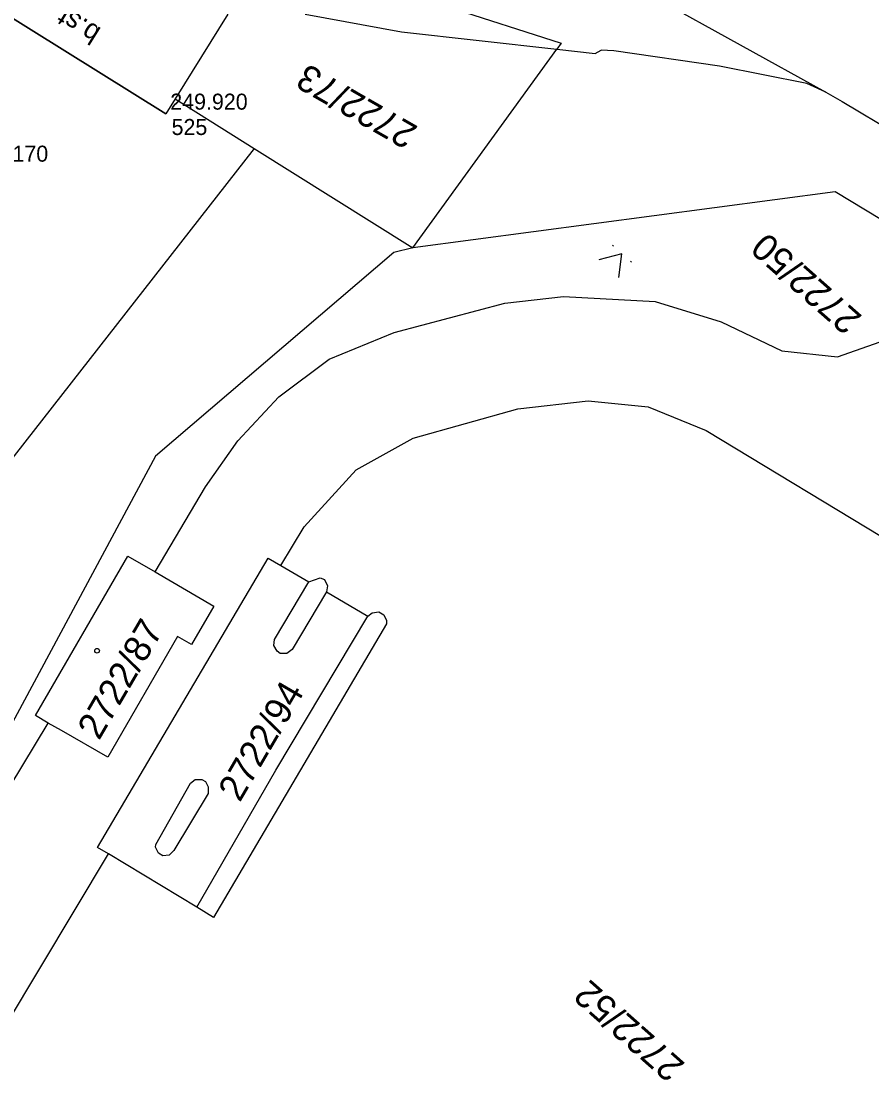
# Model space of a CAD drawing. Extents: x -496688 to -495455, y -1089309 to -1088026.
# Drawn here: x -495849.8 to -495786, y -1088485.3 to -1088405.9 of the extents above; entities that cross this region are included whole.
import ezdxf

# ---------------------------------------------------------------- set-up
doc = ezdxf.new("R2010")
doc.units = 0
for name, color, linetype in [('Vrstva 23', 7, 'Continuous'), ('Vrstva 53', 7, 'Continuous'), ('Vrstva 55', 7, 'Continuous'), ('Vrstva 56', 7, 'Continuous'), ('Vrstva 57', 7, 'Continuous'), ('Vrstva 58', 7, 'Continuous'), ('Vrstva 59', 7, 'Continuous'), ('Vrstva 60', 7, 'Continuous'), ('Vrstva 61', 7, 'Continuous')]:
    doc.layers.add(name, color=color, linetype=linetype)

msp = doc.modelspace()

# ---------------------------------------------------------------- linework, layer by layer
at = {"layer": 'Vrstva 23'}
for p, q in [((-495838.95, -1088412.85), (-495854.72, -1088403.04)), ((-495834.31, -1088405.39), (-495838.26, -1088411.74)), ((-495838.26, -1088411.74), (-495838.95, -1088412.85)), ((-495848.73, -1088457.96), (-495841.81, -1088446.01)), ((-495841.81, -1088446.01), (-495839.76, -1088447.2)), ((-495839.76, -1088447.2), (-495835.35, -1088449.77)), ((-495835.35, -1088449.77), (-495837.03, -1088452.64)), ((-495838.07, -1088452.04), (-495843.3, -1088461.09)), ((-495837.03, -1088452.64), (-495838.07, -1088452.04)), ((-495847.77, -1088458.53), (-495848.73, -1088457.96)), ((-495846.78, -1088459.09), (-495847.77, -1088458.53)), ((-495843.3, -1088461.09), (-495846.78, -1088459.09))]:
    msp.add_line(p, q, dxfattribs=at)
at = {"layer": 'Vrstva 53'}
for p, q in [((-495854.72, -1088403.04), (-495838.95, -1088412.85)), ((-495838.26, -1088411.74), (-495838.95, -1088412.85)), ((-495838.26, -1088411.74), (-495832.32, -1088415.46)), ((-495832.32, -1088415.46), (-495856.5, -1088446.39))]:
    msp.add_line(p, q, dxfattribs=at)
at = {"layer": 'Vrstva 55'}
for p, q in [((-495818.51, -1088395.14), (-495789.48, -1088411.23)), ((-495828.5, -1088405.37), (-495821.29, -1088406.71)), ((-495817.9, -1088404.8), (-495809.31, -1088407.56)), ((-495821.29, -1088406.71), (-495809.63, -1088408)), ((-495809.31, -1088407.56), (-495809.63, -1088408)), ((-495820.43, -1088422.89), (-495809.63, -1088408)), ((-495809.63, -1088408), (-495806.76, -1088408.32)), ((-495806.76, -1088408.32), (-495806.33, -1088408.09)), ((-495805.36, -1088408.14), (-495806.33, -1088408.09)), ((-495797.45, -1088409.29), (-495805.36, -1088408.14)), ((-495790.91, -1088410.59), (-495797.45, -1088409.29)), ((-495789.48, -1088411.23), (-495790.91, -1088410.59)), ((-495789.48, -1088411.23), (-495788.25, -1088411.92)), ((-495788.25, -1088411.92), (-495734.16, -1088444.4)), ((-495832.32, -1088415.46), (-495820.43, -1088422.89)), ((-495788.77, -1088418.71), (-495820.43, -1088422.89)), ((-495779.45, -1088424.37), (-495788.77, -1088418.71)), ((-495821.85, -1088423.26), (-495839.72, -1088438.53)), ((-495820.43, -1088422.89), (-495821.85, -1088423.26)), ((-495813.54, -1088427.04), (-495809.14, -1088426.54)), ((-495809.14, -1088426.54), (-495802.28, -1088426.92)), ((-495821.83, -1088429.25), (-495813.54, -1088427.04)), ((-495802.28, -1088426.92), (-495797.33, -1088428.45)), ((-495797.33, -1088428.45), (-495792.78, -1088430.61)), ((-495826.72, -1088431.25), (-495821.83, -1088429.25)), ((-495788.6, -1088431.07), (-495784.99, -1088429.8)), ((-495792.78, -1088430.61), (-495788.6, -1088431.07)), ((-495830.48, -1088434.07), (-495826.72, -1088431.25)), ((-495833.56, -1088437.37), (-495830.48, -1088434.07)), ((-495812.56, -1088434.98), (-495807.29, -1088434.37)), ((-495807.29, -1088434.37), (-495802.8, -1088434.81)), ((-495820.42, -1088437.16), (-495812.56, -1088434.98)), ((-495802.8, -1088434.81), (-495798.45, -1088436.59)), ((-495798.45, -1088436.59), (-495751.96, -1088464.75)), ((-495835.98, -1088440.81), (-495833.56, -1088437.37)), ((-495824.68, -1088439.55), (-495820.42, -1088437.16)), ((-495839.72, -1088438.53), (-495862.56, -1088480.87)), ((-495828.58, -1088443.81), (-495824.68, -1088439.55)), ((-495839.76, -1088447.2), (-495835.98, -1088440.81)), ((-495830.32, -1088446.72), (-495828.58, -1088443.81)), ((-495844.08, -1088467.85), (-495831.28, -1088446.17)), ((-495831.28, -1088446.17), (-495830.32, -1088446.72)), ((-495830.32, -1088446.72), (-495828.24, -1088447.93)), ((-495828.24, -1088447.93), (-495827.39, -1088447.64)), ((-495827.39, -1088447.64), (-495827.07, -1088447.76)), ((-495827.07, -1088447.76), (-495826.83, -1088448.23)), ((-495826.83, -1088448.23), (-495826.91, -1088448.7)), ((-495826.91, -1088448.7), (-495829.48, -1088453.01)), ((-495826.91, -1088448.7), (-495823.8, -1088450.52)), ((-495830.71, -1088462.07), (-495823.8, -1088450.52)), ((-495823.8, -1088450.52), (-495823.48, -1088450.26)), ((-495823.48, -1088450.26), (-495822.99, -1088450.19)), ((-495822.99, -1088450.19), (-495822.6, -1088450.41)), ((-495822.6, -1088450.41), (-495822.4, -1088450.84)), ((-495822.4, -1088451.08), (-495835.39, -1088473.11)), ((-495822.4, -1088450.84), (-495822.4, -1088451.08)), ((-495853.67, -1088468.28), (-495847.77, -1088458.53)), ((-495835.79, -1088463.81), (-495838.36, -1088468.09)), ((-495843.26, -1088468.34), (-495844.08, -1088467.85)), ((-495850.9, -1088481.1), (-495843.26, -1088468.34)), ((-495836.62, -1088472.33), (-495843.26, -1088468.34)), ((-495835.39, -1088473.11), (-495836.62, -1088472.33))]:
    msp.add_line(p, q, dxfattribs=at)
at = {"layer": 'Vrstva 56'}
for p, q in [((-495830.81, -1088452.26), (-495828.24, -1088447.93)), ((-495830.86, -1088452.71), (-495830.81, -1088452.26)), ((-495830.61, -1088453.14), (-495830.86, -1088452.71)), ((-495829.48, -1088453.01), (-495829.89, -1088453.31)), ((-495830.37, -1088453.32), (-495830.61, -1088453.14)), ((-495829.89, -1088453.31), (-495830.37, -1088453.32)), ((-495836.62, -1088472.33), (-495830.71, -1088462.07)), ((-495839.71, -1088467.62), (-495837.1, -1088463.04)), ((-495837.1, -1088463.04), (-495836.75, -1088462.75)), ((-495836.75, -1088462.75), (-495836.25, -1088462.77)), ((-495836.25, -1088462.77), (-495835.98, -1088462.92)), ((-495835.98, -1088462.92), (-495835.79, -1088463.3)), ((-495835.79, -1088463.3), (-495835.79, -1088463.81)), ((-495839.73, -1088467.84), (-495839.71, -1088467.62)), ((-495839.49, -1088468.29), (-495839.73, -1088467.84)), ((-495838.36, -1088468.09), (-495838.7, -1088468.42)), ((-495839.17, -1088468.49), (-495839.49, -1088468.29)), ((-495838.7, -1088468.42), (-495839.17, -1088468.49))]:
    msp.add_line(p, q, dxfattribs=at)
at = {"layer": 'Vrstva 58'}
for p, q in [((-495805.397, -1088422.78), (-495805.472, -1088422.714)), ((-495804.046, -1088423.97), (-495804.121, -1088423.904))]:
    msp.add_line(p, q, dxfattribs=at)
msp.add_lwpolyline([(-495805, -1088425.129), (-495804.759, -1088423.342), (-495806.501, -1088423.807)], dxfattribs=at)
at = {"layer": 'Vrstva 59'}
msp.add_circle((-495844.109, -1088453.103), 0.175, dxfattribs=at)
at = {"layer": 'Vrstva 60'}
msp.add_line((-495838.92, -1088412.84), (-495838.92, -1088412.84), dxfattribs=at)

# ---------------------------------------------------------------- texts
at = {"layer": 'Vrstva 23'}
msp.add_text('b.st.', height=1.5, rotation=148.11561, dxfattribs=at).set_placement((-495843.727, -1088406.473))
at = {"layer": 'Vrstva 57'}
for s, rotation, p in [('2722/73', 150.18359, (-495819.969, -1088413.845)), ('2722/50', 138.5264, (-495786.679, -1088428.046)), ('2722/87', 59.70676, (-495843.956, -1088459.883)), ('2722/94', 59.70676, (-495833.406, -1088464.526)), ('2722/52', 138.5264, (-495799.953, -1088484.079))]:
    msp.add_text(s, height=2, rotation=rotation, dxfattribs=at).set_placement(p)
at = {"layer": 'Vrstva 60'}
msp.add_text('525', height=1.2, dxfattribs=at).set_placement((-495838.52, -1088414.44))
at = {"layer": 'Vrstva 61'}
for s, p in [('249.920', (-495838.62, -1088412.54)), ('250.170', (-495853.57, -1088416.44))]:
    msp.add_text(s, height=1.2, dxfattribs=at).set_placement(p)

doc.saveas('drawing.dxf')
